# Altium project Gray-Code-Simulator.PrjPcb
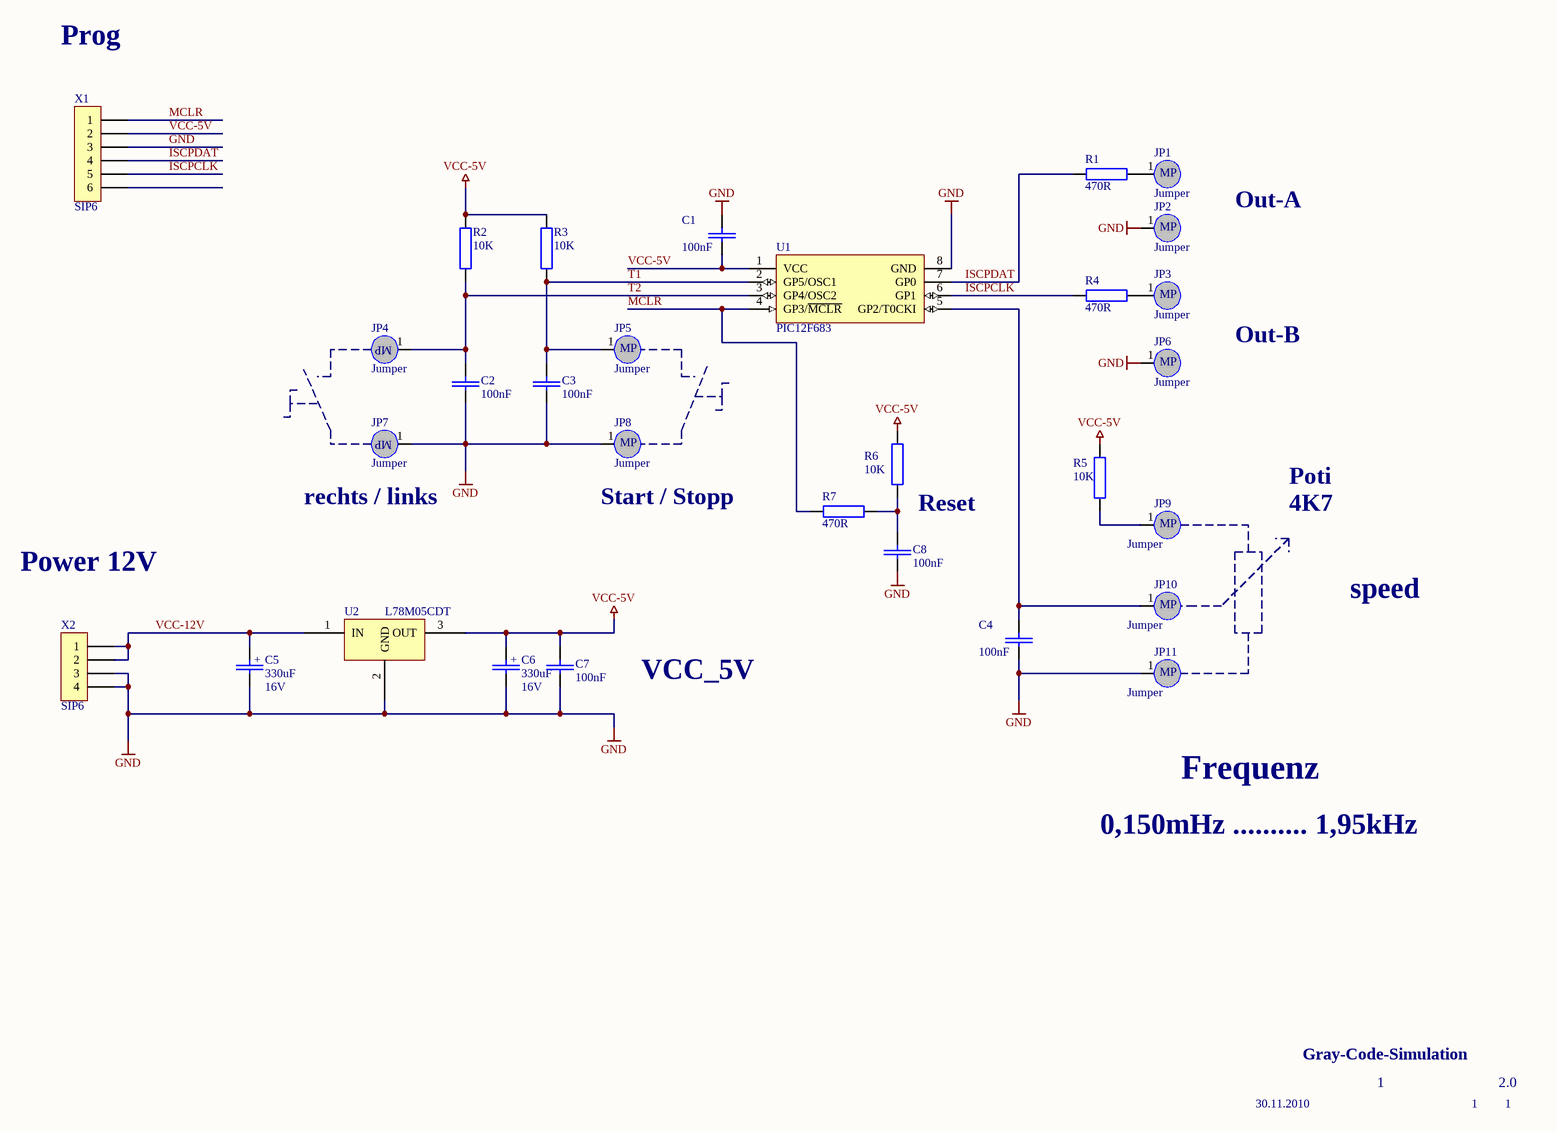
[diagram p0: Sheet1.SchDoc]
1 sheet, 30 parts. Net scope: global (net labels, ports and power ports of the same name join across sheets).
Board file: Gray-Code-Simulator.PcbDoc

## Sheet Sheet1.SchDoc
size A3; Organization: Altium Limited; Address1: MK; PageSetup: Record=PageOptions|CenterHorizontal=True|CenterVertical=True|PrintScale=0.69|XCorrection=1.00|YCorrection=1.00|PrintKind=2|BorderSize=5000000|LeftOffset=0|BottomOffset=0|Orientation=2|PaperLength=1000|PaperWidth=1000|Scale=100|PaperSource=7|PrintQuality=-4|MediaType=1|DitherType=10|PaperKind=A4|PrintScaleMode=1

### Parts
C1  100nF  [RAD0.2]
C2  100nF  [RAD0.2]
C3  100nF  [RAD0.2]
C4  100nF  [RAD0.2]
C5  330uF  TechSpannung: 16V  [ELK_RM035_8x11.5]
C6  330uF  TechSpannung: 16V  [ELK_RM035_8x11.5]
C7  100nF  [RAD0.2]
C8  100nF  [RAD0.2]
JP1  Jumper  [SIP1]
JP2  Jumper  [SIP1]
JP3  Jumper  [SIP1]
JP4  Jumper  [SIP1]
JP5  Jumper  [SIP1]
JP6  Jumper  [SIP1]
JP7  Jumper  [SIP1]
JP8  Jumper  [SIP1]
JP9  Jumper  [SIP1]
JP10  Jumper  [SIP1]
JP11  Jumper  [SIP1]
R1  470R  [R0207]
R2  10K  [R0207]
R3  10K  [R0207]
R4  470R  [R0207]
R5  10K  [R0207]
R6  10K  [R0207]
R7  470R  [R0207]
U1  PIC12F683  [DIP8]
U2  L78M05CDT  [TO-92A]
X1  SIP6  [SIP6]
X2  SIP6  [SIP4]

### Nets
GND: C1.1 C2.2 C3.2 C4.2 C5.2 C6.2 C7.2 C8.2 JP2.1 JP6.1 JP7.1 JP8.1 JP11.1 U1.8(GND) U2.2(GND) X1.3 X2.3 X2.4
VCC-5V: C1.2 C6.1 C7.1 R2.1 R3.1 R5.1 R6.1 U1.1(VCC) U2.3(OUT) X1.2
ISCPCLK: R4.1 U1.6(GP1) X1.5
ISCPDAT: R1.1 U1.7(GP0) X1.4
MCLR: R7.1 U1.4(GP3/~{MCLR}) X1.1
T1: C3.1 JP5.1 R3.2 U1.2(GP5/OSC1)
T2: C2.1 JP4.1 R2.2 U1.3(GP4/OSC2)
VCC-12V: C5.1 U2.1(IN) X2.1 X2.2
NetC4_1: C4.1 JP10.1 U1.5(GP2/T0CKI)
NetC8_1: C8.1 R6.2 R7.2
NetJP1_1: JP1.1 R1.2
NetJP3_1: JP3.1 R4.2
NetJP9_1: JP9.1 R5.2

Not connected (* = marked no-connect by the designer): X1 6

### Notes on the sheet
- Prog
- Out-A
- Out-B
- (near JP7) rechts / links
- Start / Stopp
- Poti
- Reset
- 4K7
- Power 12V
- speed
- VCC_5V
- 0,150mHz .......... 1,95kHz
- Frequenz
- 30.11.2010
- Gray-Code-Simulation
- 1
- 2.0

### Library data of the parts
C1-C4 C7 C8 = 100NF_RM05: Capacitor; Voltage: 63V; Class: passive; Tolerance: *%; SAP No.: 6507 3030
C5 C6 = 330UF_RM3.5_16V: Capacitor Aluminum Electrolytic 330UF, 16V 105°C , Low Impedance; Manufacturer: RUBYCON; Tolerance: 20%; Class: passive; Note: RoHS konf. / Low Impedance; Herst. Bezeichnung: 16YXF330xxxx 8X11.5
JP1-JP11 = JUMPER1: Lötauge; Class: passive; SubClass: Connector
R1-R7 = DUMMY_RM1016: Resistor Axial; Power: *W; Voltage: *V; Tolerance: *%; Class: passive
U1 = PIC12C508-04_SO-8: 8-BIT CMOS Microcontroller, 8-PIN,; Manufacturer: MICROCHIP; Part No.: 1196846; SAP No.: 6506 3546; Note: RoHS konf. /; Class: active; Herst. Bezeichnung: PIC12C508-04I/SM
U2 = 78M05_TO252: Voltage Regulators 5V SMD; Manufacturer: STM; Part No.: 1087116; SAP No.: 6506 3547; Class: active; Note: RoHS konf. /
X1 = SIP6: Stiftleiste, 6-Pin; Class: passive; SubClass: Connector
X2 = SIP4: Stiftleiste, 4-Pin; Class: passive; Note: Lötaugen; SubClass: Connector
